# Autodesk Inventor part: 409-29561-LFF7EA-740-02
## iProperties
Created: 2010-06
Part Number: 409-29561-LFF7EA-740-02
Material: Sch40 CS PIPE SEAMLESS
Description: PIPE
Document SubType Name: Modeling
Designer: S. Boerckel
Engineer: Steve Boerckel
Mass: 6532.87 g
Surface Area: 2805.88 cm^2
Volume: 832.213 cm^3
Density: 7.85 g/cm^3
Cost Center: 4"
SMR: =<COST CENTER> - <Material>
Length: 16.000 in
Title: 4"
Author: S. Boerckel
Revision Number: B
Subject: DEMIN WATER FORWARDING PUMP SKID-7EA
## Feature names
1. Extrusion1
